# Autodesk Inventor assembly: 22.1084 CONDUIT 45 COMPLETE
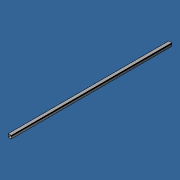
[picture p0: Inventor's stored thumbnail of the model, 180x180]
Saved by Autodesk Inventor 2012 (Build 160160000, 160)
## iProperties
Created: 2016-03
Part Number: 22.1084 CONDUIT 45 COMPLETE
Document SubType Name: Assembly
Designer: Admin
Author: Admin
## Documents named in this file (3)
- C:\Andys Backup Data\ANDY'S INVENTOR\INVENTOR LIBRARIES\PARTS LIBRARY\ELECTRICAL INSTALLATION\22.1084 CONDUIT 45 COMPLETE.iam
- C:\Andys Backup Data\ANDY'S INVENTOR\INVENTOR LIBRARIES\PARTS LIBRARY\ELECTRICAL INSTALLATION\22.1084 CONDUIT 45 BOTTOM.ipt
- C:\Andys Backup Data\ANDY'S INVENTOR\INVENTOR LIBRARIES\PARTS LIBRARY\ELECTRICAL INSTALLATION\22.1084 CONDUIT 45 TOP.ipt
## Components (2 placed, 2 different names)
1. 22.1084 CONDUIT 45 BOTTOM:1 — Flush:1, Mate:1, Flush:2
2. 22.1084 CONDUIT 45 TOP:1 — Flush:1, Mate:1, Flush:2
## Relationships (3: Flush 2, Mate 1)
- Flush:1: 22.1084 CONDUIT 45 BOTTOM:1 ↔ 22.1084 CONDUIT 45 TOP:1
- Mate:1: 22.1084 CONDUIT 45 BOTTOM:1 ↔ 22.1084 CONDUIT 45 TOP:1
- Flush:2: 22.1084 CONDUIT 45 BOTTOM:1 ↔ 22.1084 CONDUIT 45 TOP:1
